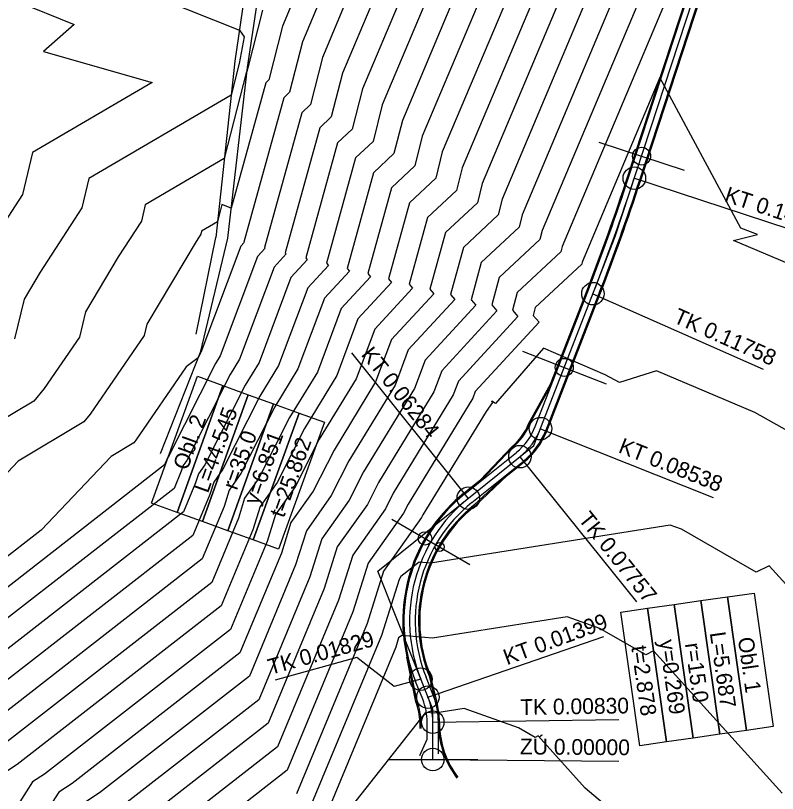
# Model space of a CAD drawing. Extents: x -549394 to -546608, y -1037055 to -1033629.
# Drawn here: x -548832.9 to -548663.6, y -1034374.1 to -1034201.2 of the extents above; entities that cross this region are included whole.
import ezdxf

# ---------------------------------------------------------------- set-up
doc = ezdxf.new("R2010")
doc.units = 0
for name, color, linetype in [('hlavni_vrst', 7, 'Continuous'), ('hrana_L', 7, 'Continuous'), ('norm_vrst', 7, 'Continuous'), ('POLYGONY_SITUACE_PO', 7, 'Continuous'), ('u_sirka_0_5m', 7, 'Continuous'), ('u_sirka_1_5m', 7, 'Continuous'), ('x_navrh_C122', 7, 'Continuous'), ('x_osa_C122', 7, 'Continuous'), ('x_popis_oblouky_C122', 7, 'Continuous'), ('x_popis_pricne_rezy_C122', 7, 'Continuous')]:
    doc.layers.add(name, color=color, linetype=linetype)

msp = doc.modelspace()

# ---------------------------------------------------------------- linework, layer by layer
at = {"layer": 'hlavni_vrst'}
for p, q in [((-548704.96, -1034195.08), (-548724.74, -1034242.04)), ((-548735.22, -1034196.67), (-548746.95, -1034224.54)), ((-548765.47, -1034198.27), (-548769.17, -1034207.05)), ((-548769.17, -1034207.05), (-548772.01, -1034218.28)), ((-548773.32, -1034219.5), (-548782.21, -1034251.62)), ((-548772.01, -1034218.28), (-548773.32, -1034219.5)), ((-548746.95, -1034224.54), (-548748.82, -1034231.91)), ((-548748.82, -1034231.91), (-548753.35, -1034236.16)), ((-548753.35, -1034236.16), (-548759.23, -1034257.42)), ((-548724.74, -1034242.04), (-548725.63, -1034245.55)), ((-548725.63, -1034245.55), (-548733.38, -1034252.81)), ((-548782.14, -1034251.7), (-548782.88, -1034252.51)), ((-548782.21, -1034251.62), (-548782.14, -1034251.7)), ((-548782.88, -1034252.51), (-548791.77, -1034276.13)), ((-548733.38, -1034252.81), (-548736.26, -1034263.23)), ((-548759.23, -1034257.42), (-548758.71, -1034258.01)), ((-548758.71, -1034258.01), (-548764.26, -1034264.03)), ((-548764.26, -1034264.03), (-548770.17, -1034279.76)), ((-548735.29, -1034264.33), (-548745.63, -1034275.56)), ((-548736.26, -1034263.23), (-548735.29, -1034264.33)), ((-548791.8, -1034276.18), (-548792.38, -1034277.32)), ((-548791.77, -1034276.13), (-548791.8, -1034276.18)), ((-548745.63, -1034275.56), (-548748.57, -1034283.39)), ((-548715.59, -1034275.15), (-548726.21, -1034287.49)), ((-548701.85, -1034281.06), (-548715.59, -1034275.15)), ((-548792.38, -1034277.32), (-548795, -1034279.32)), ((-548795, -1034279.32), (-548806.18, -1034295.61)), ((-548770.17, -1034279.76), (-548775.33, -1034288.2)), ((-548698.68, -1034282.78), (-548701.85, -1034281.06)), ((-548690.48, -1034280.2), (-548698.68, -1034282.78)), ((-548668.6, -1034289.46), (-548690.48, -1034280.2)), ((-548748.57, -1034283.39), (-548758.85, -1034300.21)), ((-548727.05, -1034286.95), (-548727.13, -1034286.99)), ((-548727.13, -1034286.99), (-548726.89, -1034287.22)), ((-548726.21, -1034287.49), (-548727.05, -1034286.95)), ((-548775.33, -1034288.2), (-548782.83, -1034303.04)), ((-548726.89, -1034287.22), (-548728.35, -1034289.27)), ((-548728.35, -1034289.27), (-548742.37, -1034312.23)), ((-548654.02, -1034297.71), (-548668.6, -1034289.46)), ((-548806.18, -1034295.61), (-548806.67, -1034296.2)), ((-548806.67, -1034296.2), (-548811.72, -1034299.21)), ((-548811.72, -1034299.21), (-548827.23, -1034315.61)), ((-548758.85, -1034300.21), (-548762.75, -1034307.93)), ((-548782.83, -1034303.04), (-548785.44, -1034306.72)), ((-548785.44, -1034306.72), (-548786.57, -1034310.32)), ((-548762.75, -1034307.93), (-548768.28, -1034315.73)), ((-548786.57, -1034310.32), (-548791.42, -1034322)), ((-548742.68, -1034312.83), (-548751.12, -1034324.74)), ((-548742.37, -1034312.23), (-548742.68, -1034312.83)), ((-548827.23, -1034315.61), (-548875.4, -1034353.08)), ((-548768.28, -1034315.73), (-548770.67, -1034323.35)), ((-548791.42, -1034322), (-548844.83, -1034363.54)), ((-548770.67, -1034323.35), (-548780.95, -1034348.1)), ((-548751.12, -1034324.74), (-548754.77, -1034336.39)), ((-548754.77, -1034336.39), (-548770.49, -1034374.21)), ((-548780.95, -1034348.1), (-548814.25, -1034374.01)), ((-548814.25, -1034374.01), (-548817.51, -1034376.13))]:
    msp.add_line(p, q, dxfattribs=at)
at = {"layer": 'hrana_L'}
for p, q in [((-548782.05, -1034196.95), (-548784.21, -1034211.37)), ((-548779.39, -1034199), (-548781.43, -1034212.74)), ((-548784.21, -1034211.37), (-548788.45, -1034250.58)), ((-548781.43, -1034212.74), (-548785.79, -1034250.71)), ((-548792.82, -1034272.02), (-548788.45, -1034250.58)), ((-548785.79, -1034250.71), (-548791.9, -1034276.11)), ((-548791.9, -1034276.11), (-548800.78, -1034298.66))]:
    msp.add_line(p, q, dxfattribs=at)
at = {"layer": 'norm_vrst'}
for p, q in [((-548698.91, -1034194.76), (-548720.29, -1034245.54)), ((-548692.86, -1034194.44), (-548715.85, -1034249.04)), ((-548686.81, -1034194.12), (-548711.41, -1034252.54)), ((-548741.27, -1034196.99), (-548751.4, -1034221.04)), ((-548729.17, -1034196.35), (-548742.51, -1034228.04)), ((-548723.11, -1034196.04), (-548738.07, -1034231.54)), ((-548717.06, -1034195.72), (-548733.62, -1034235.04)), ((-548711.01, -1034195.4), (-548729.18, -1034238.54)), ((-548832.73, -1034198.05), (-548819.92, -1034203.21)), ((-548800.85, -1034197.36), (-548783.18, -1034204.48)), ((-548771.52, -1034198.59), (-548773.61, -1034203.55)), ((-548759.42, -1034197.95), (-548764.73, -1034210.55)), ((-548753.37, -1034197.63), (-548760.28, -1034214.05)), ((-548747.32, -1034197.31), (-548755.84, -1034217.55)), ((-548778.06, -1034200.05), (-548781.29, -1034212.82)), ((-548819.92, -1034203.21), (-548826.7, -1034209.23)), ((-548773.61, -1034203.55), (-548776.65, -1034215.55)), ((-548783.18, -1034204.48), (-548782.11, -1034205.98)), ((-548782.11, -1034205.98), (-548783.22, -1034211.86)), ((-548826.7, -1034209.23), (-548802.58, -1034216.08)), ((-548764.73, -1034210.55), (-548767.37, -1034221)), ((-548783.22, -1034211.86), (-548785.03, -1034218.96)), ((-548781.59, -1034213.63), (-548786.55, -1034233.01)), ((-548781.53, -1034213.65), (-548781.59, -1034213.63)), ((-548781.31, -1034212.84), (-548781.53, -1034213.65)), ((-548781.29, -1034212.82), (-548781.31, -1034212.84)), ((-548760.28, -1034214.05), (-548762.74, -1034223.73)), ((-548802.58, -1034216.08), (-548829.17, -1034231.66)), ((-548776.65, -1034215.55), (-548777.32, -1034216.17)), ((-548689.68, -1034214.99), (-548706.96, -1034256.04)), ((-548671.73, -1034248.5), (-548689.68, -1034214.99)), ((-548777.32, -1034216.17), (-548785.02, -1034244.03)), ((-548755.84, -1034217.55), (-548758.1, -1034226.46)), ((-548785.03, -1034218.96), (-548816.64, -1034237.48)), ((-548767.37, -1034221), (-548769.33, -1034222.83)), ((-548751.4, -1034221.04), (-548753.46, -1034229.19)), ((-548769.33, -1034222.83), (-548777.61, -1034252.78)), ((-548762.74, -1034223.73), (-548765.33, -1034226.16)), ((-548765.33, -1034226.16), (-548773.02, -1034253.94)), ((-548758.1, -1034226.46), (-548761.34, -1034229.49)), ((-548742.51, -1034228.04), (-548744.18, -1034234.64)), ((-548761.34, -1034229.49), (-548768.42, -1034255.1)), ((-548753.46, -1034229.19), (-548757.35, -1034232.83)), ((-548829.17, -1034231.66), (-548831.41, -1034241.01)), ((-548738.07, -1034231.54), (-548739.54, -1034237.37)), ((-548786.55, -1034233.01), (-548804.11, -1034243.3)), ((-548757.35, -1034232.83), (-548763.83, -1034256.26)), ((-548744.18, -1034234.64), (-548749.36, -1034239.49)), ((-548733.62, -1034235.04), (-548734.9, -1034240.1)), ((-548816.64, -1034237.48), (-548818.19, -1034243.95)), ((-548739.54, -1034237.37), (-548745.36, -1034242.82)), ((-548729.18, -1034238.54), (-548730.26, -1034242.82)), ((-548749.36, -1034239.49), (-548754.64, -1034258.58)), ((-548734.9, -1034240.1), (-548741.37, -1034246.15)), ((-548831.41, -1034241.01), (-548844.45, -1034261.12)), ((-548804.11, -1034243.3), (-548804.97, -1034246.9)), ((-548787.08, -1034243.19), (-548788.07, -1034247.07)), ((-548785.02, -1034244.03), (-548787.08, -1034243.19)), ((-548745.36, -1034242.82), (-548750.05, -1034259.74)), ((-548730.26, -1034242.82), (-548737.38, -1034249.48)), ((-548818.19, -1034243.95), (-548827.46, -1034258.25)), ((-548804.97, -1034246.9), (-548810.12, -1034254.84)), ((-548788.07, -1034247.07), (-548791.58, -1034249.12)), ((-548741.37, -1034246.15), (-548745.45, -1034260.9)), ((-548720.29, -1034245.54), (-548720.99, -1034248.28)), ((-548720.99, -1034248.28), (-548729.39, -1034256.14)), ((-548667.97, -1034249.87), (-548671.73, -1034248.5)), ((-548791.75, -1034249.84), (-548792.78, -1034251.43)), ((-548791.58, -1034249.12), (-548791.75, -1034249.84)), ((-548737.38, -1034249.48), (-548740.86, -1034262.07)), ((-548715.85, -1034249.04), (-548716.35, -1034251.01)), ((-548673.3, -1034251.25), (-548667.97, -1034249.87)), ((-548792.78, -1034251.43), (-548803.75, -1034269.81)), ((-548716.35, -1034251.01), (-548725.39, -1034259.47)), ((-548654.22, -1034259.32), (-548673.3, -1034251.25)), ((-548777.45, -1034252.96), (-548779.16, -1034254.81)), ((-548777.61, -1034252.78), (-548777.45, -1034252.96)), ((-548773.02, -1034253.94), (-548772.77, -1034254.22)), ((-548711.71, -1034253.73), (-548721.4, -1034262.8)), ((-548711.41, -1034252.54), (-548711.71, -1034253.73)), ((-548810.12, -1034254.84), (-548817.41, -1034267.05)), ((-548779.16, -1034254.81), (-548787.45, -1034276.86)), ((-548772.77, -1034254.22), (-548775.43, -1034257.12)), ((-548768.08, -1034255.49), (-548771.71, -1034259.42)), ((-548768.42, -1034255.1), (-548768.08, -1034255.49)), ((-548775.43, -1034257.12), (-548783.13, -1034277.58)), ((-548763.4, -1034256.75), (-548767.98, -1034261.73)), ((-548763.83, -1034256.26), (-548763.4, -1034256.75)), ((-548729.39, -1034256.14), (-548731.67, -1034264.39)), ((-548707.07, -1034256.46), (-548717.41, -1034266.14)), ((-548706.96, -1034256.04), (-548707.07, -1034256.46)), ((-548827.46, -1034258.25), (-548831.06, -1034264.29)), ((-548754.03, -1034259.28), (-548760.53, -1034266.34)), ((-548754.64, -1034258.58), (-548754.03, -1034259.28)), ((-548771.71, -1034259.42), (-548778.81, -1034278.31)), ((-548749.34, -1034260.54), (-548756.81, -1034268.64)), ((-548750.05, -1034259.74), (-548749.34, -1034260.54)), ((-548745.45, -1034260.9), (-548744.66, -1034261.81)), ((-548725.39, -1034259.47), (-548727.07, -1034265.55)), ((-548767.98, -1034261.73), (-548774.49, -1034279.04)), ((-548744.66, -1034261.81), (-548753.08, -1034270.95)), ((-548740.86, -1034262.07), (-548739.98, -1034263.07)), ((-548721.4, -1034262.8), (-548722.48, -1034266.71)), ((-548831.06, -1034264.29), (-548833.16, -1034273.12)), ((-548739.98, -1034263.07), (-548749.35, -1034273.25)), ((-548731.67, -1034264.39), (-548730.61, -1034265.6)), ((-548730.61, -1034265.6), (-548741.9, -1034277.86)), ((-548727.07, -1034265.55), (-548725.92, -1034266.86)), ((-548717.41, -1034266.14), (-548717.89, -1034267.87)), ((-548817.41, -1034267.05), (-548818.75, -1034272.73)), ((-548760.53, -1034266.34), (-548765.85, -1034280.49)), ((-548725.92, -1034266.86), (-548738.18, -1034280.17)), ((-548722.48, -1034266.71), (-548721.24, -1034268.12)), ((-548717.89, -1034267.87), (-548716.55, -1034269.39)), ((-548756.81, -1034268.64), (-548761.53, -1034281.21)), ((-548721.24, -1034268.12), (-548734.45, -1034282.47)), ((-548716.55, -1034269.39), (-548730.73, -1034284.78)), ((-548803.75, -1034269.81), (-548804.35, -1034272.34)), ((-548753.08, -1034270.95), (-548757.21, -1034281.94)), ((-548818.75, -1034272.73), (-548826.56, -1034284.1)), ((-548804.35, -1034272.34), (-548816.37, -1034289.86)), ((-548749.35, -1034273.25), (-548752.89, -1034282.66)), ((-548787.45, -1034276.86), (-548788.51, -1034278.59)), ((-548783.13, -1034277.58), (-548785.21, -1034280.99)), ((-548778.81, -1034278.31), (-548781.92, -1034283.39)), ((-548741.9, -1034277.86), (-548744.26, -1034284.12)), ((-548788.51, -1034278.59), (-548798.89, -1034299.12)), ((-548774.49, -1034279.04), (-548778.62, -1034285.8)), ((-548785.21, -1034280.99), (-548794.88, -1034300.1)), ((-548765.85, -1034280.49), (-548772.03, -1034290.6)), ((-548761.53, -1034281.21), (-548768.74, -1034293)), ((-548738.18, -1034280.17), (-548739.94, -1034284.84)), ((-548781.92, -1034283.39), (-548790.86, -1034301.08)), ((-548757.21, -1034281.94), (-548765.44, -1034295.41)), ((-548752.89, -1034282.66), (-548762.14, -1034297.81)), ((-548734.45, -1034282.47), (-548735.62, -1034285.57)), ((-548826.56, -1034284.1), (-548828.91, -1034286.91)), ((-548744.26, -1034284.12), (-548755.55, -1034302.62)), ((-548739.94, -1034284.84), (-548752.26, -1034305.02)), ((-548730.73, -1034284.78), (-548731.3, -1034286.29)), ((-548828.91, -1034286.91), (-548852.99, -1034301.31)), ((-548778.62, -1034285.8), (-548786.85, -1034302.06)), ((-548735.62, -1034285.57), (-548748.96, -1034307.42)), ((-548731.3, -1034286.29), (-548745.67, -1034309.83)), ((-548816.37, -1034289.86), (-548817.79, -1034291.55)), ((-548817.79, -1034291.55), (-548832.35, -1034300.26)), ((-548772.03, -1034290.6), (-548778.82, -1034304.02)), ((-548768.74, -1034293), (-548774.8, -1034305)), ((-548765.44, -1034295.41), (-548770.78, -1034305.97)), ((-548798.89, -1034299.12), (-548799.17, -1034299.51)), ((-548762.14, -1034297.81), (-548766.77, -1034306.95)), ((-548832.35, -1034300.26), (-548877.14, -1034347.58)), ((-548799.29, -1034299.89), (-548799.8, -1034301.11)), ((-548799.17, -1034299.51), (-548799.29, -1034299.89)), ((-548794.88, -1034300.1), (-548795.74, -1034301.31)), ((-548799.8, -1034301.11), (-548869.29, -1034355.17)), ((-548796.11, -1034302.49), (-548797.7, -1034306.33)), ((-548795.74, -1034301.31), (-548796.11, -1034302.49)), ((-548790.86, -1034301.08), (-548792.3, -1034303.11)), ((-548786.85, -1034302.06), (-548788.87, -1034304.91)), ((-548792.3, -1034303.11), (-548792.93, -1034305.1)), ((-548778.82, -1034304.02), (-548782.01, -1034308.52)), ((-548755.55, -1034302.62), (-548758.74, -1034308.91)), ((-548792.93, -1034305.1), (-548795.61, -1034311.56)), ((-548788.87, -1034304.91), (-548789.75, -1034307.71)), ((-548774.8, -1034305), (-548778.58, -1034310.32)), ((-548770.78, -1034305.97), (-548775.15, -1034312.13)), ((-548752.26, -1034305.02), (-548754.72, -1034309.89)), ((-548797.7, -1034306.33), (-548863.17, -1034357.27)), ((-548789.75, -1034307.71), (-548793.52, -1034316.78)), ((-548766.77, -1034306.95), (-548771.71, -1034313.93)), ((-548748.96, -1034307.42), (-548750.71, -1034310.87)), ((-548782.01, -1034308.52), (-548783.39, -1034312.92)), ((-548758.74, -1034308.91), (-548764.85, -1034317.53)), ((-548778.58, -1034310.32), (-548780.21, -1034315.53)), ((-548754.72, -1034309.89), (-548761.42, -1034319.34)), ((-548750.71, -1034310.87), (-548757.99, -1034321.14)), ((-548745.67, -1034309.83), (-548746.69, -1034311.85)), ((-548795.61, -1034311.56), (-548857.06, -1034359.36)), ((-548783.39, -1034312.92), (-548789.33, -1034327.22)), ((-548775.15, -1034312.13), (-548777.03, -1034318.14)), ((-548746.69, -1034311.85), (-548754.56, -1034322.94)), ((-548771.71, -1034313.93), (-548773.85, -1034320.75)), ((-548687.4, -1034314.52), (-548740.71, -1034322.92)), ((-548684.92, -1034315.39), (-548687.4, -1034314.52)), ((-548780.21, -1034315.53), (-548787.23, -1034332.44)), ((-548668.27, -1034324.97), (-548684.92, -1034315.39)), ((-548793.52, -1034316.78), (-548850.94, -1034361.45)), ((-548777.03, -1034318.14), (-548785.14, -1034337.66)), ((-548764.85, -1034317.53), (-548767.49, -1034325.96)), ((-548761.42, -1034319.34), (-548764.31, -1034328.57)), ((-548773.85, -1034320.75), (-548783.05, -1034342.88)), ((-548757.99, -1034321.14), (-548761.13, -1034331.17)), ((-548754.56, -1034322.94), (-548757.95, -1034333.78)), ((-548743.22, -1034322.7), (-548747.27, -1034325.94)), ((-548740.71, -1034322.92), (-548743.22, -1034322.7)), ((-548665.39, -1034323.55), (-548668.27, -1034324.97)), ((-548630.74, -1034361.88), (-548665.39, -1034323.55)), ((-548767.49, -1034325.96), (-548778.86, -1034353.32)), ((-548747.69, -1034326.55), (-548751.59, -1034339)), ((-548747.27, -1034325.94), (-548747.69, -1034326.55)), ((-548789.33, -1034327.22), (-548838.71, -1034365.64)), ((-548764.31, -1034328.57), (-548776.77, -1034358.54)), ((-548761.13, -1034331.17), (-548774.67, -1034363.76)), ((-548787.23, -1034332.44), (-548832.6, -1034367.73)), ((-548757.95, -1034333.78), (-548772.58, -1034368.98)), ((-548710.3, -1034334.9), (-548740.22, -1034339.62)), ((-548703.04, -1034337.46), (-548710.3, -1034334.9)), ((-548785.14, -1034337.66), (-548826.48, -1034369.82)), ((-548692.84, -1034343.32), (-548703.04, -1034337.46)), ((-548751.59, -1034339), (-548768.39, -1034379.43)), ((-548747.77, -1034339.56), (-548748.41, -1034341.6)), ((-548747.08, -1034339), (-548747.77, -1034339.56)), ((-548740.22, -1034339.62), (-548747.08, -1034339)), ((-548748.41, -1034341.6), (-548766.3, -1034384.65)), ((-548783.05, -1034342.88), (-548820.37, -1034371.91)), ((-548691.08, -1034342.45), (-548692.84, -1034343.32)), ((-548662.5, -1034374.07), (-548691.08, -1034342.45)), ((-548778.86, -1034353.32), (-548808.14, -1034376.1)), ((-548759.56, -1034378.68), (-548741.71, -1034356.14)), ((-548739.74, -1034356.32), (-548741.71, -1034356.14)), ((-548733.19, -1034355.28), (-548739.74, -1034356.32)), ((-548721.16, -1034359.52), (-548733.19, -1034355.28)), ((-548776.77, -1034358.54), (-548802.02, -1034378.19)), ((-548717.42, -1034361.68), (-548721.16, -1034359.52)), ((-548716.77, -1034361.36), (-548717.42, -1034361.68)), ((-548706.28, -1034372.96), (-548716.77, -1034361.36)), ((-548774.67, -1034363.76), (-548795.91, -1034380.28)), ((-548832.6, -1034367.73), (-548834.97, -1034369.28)), ((-548826.48, -1034369.82), (-548829.15, -1034371.56)), ((-548772.58, -1034368.98), (-548789.79, -1034382.37)), ((-548829.15, -1034371.56), (-548842.47, -1034392.22)), ((-548820.37, -1034371.91), (-548823.33, -1034373.85)), ((-548664.52, -1034408.24), (-548706.28, -1034372.96)), ((-548823.33, -1034373.85), (-548838.11, -1034396.77))]:
    msp.add_line(p, q, dxfattribs=at)
at = {"layer": 'POLYGONY_SITUACE_PO'}
for centre in [(-548695.37, -1034237.37), (-548704.57, -1034263.05), (-548716.24, -1034293.05), (-548720.81, -1034299.28), (-548732.28, -1034308.52), (-548742.85, -1034348.75), (-548741.26, -1034352.75), (-548740.19, -1034358.3), (-548740.19, -1034366.6)]:
    msp.add_circle(centre, 2.5, dxfattribs=at)
at = {"layer": 'u_sirka_0_5m'}
for centre in [(-548693.77, -1034232.48), (-548710.94, -1034279.43)]:
    msp.add_circle(centre, 2, dxfattribs=at)
at = {"layer": 'u_sirka_1_5m'}
for centre, radius in [((-548741.9, -1034317.45), 1.5), ((-548738.66, -1034319.33), 1)]:
    msp.add_circle(centre, radius, dxfattribs=at)
at = {"layer": 'x_navrh_C122'}
for p, q in [((-548696.56, -1034236.98), (-548681.92, -1034192.29)), ((-548694.18, -1034237.76), (-548679.54, -1034193.07)), ((-548717.4, -1034292.59), (-548705.73, -1034262.6)), ((-548715.07, -1034293.5), (-548703.4, -1034263.5)), ((-548718.91, -1034291.99), (-548714, -1034283.16)), ((-548718.68, -1034292.09), (-548713.78, -1034283.27)), ((-548722.63, -1034297.07), (-548729.56, -1034304.4)), ((-548722.46, -1034297.25), (-548729.39, -1034304.59)), ((-548733.07, -1034307.55), (-548721.6, -1034298.32)), ((-548731.5, -1034309.49), (-548720.03, -1034300.26)), ((-548731.03, -1034310.08), (-548723.71, -1034303.22)), ((-548730.87, -1034310.27), (-548723.54, -1034303.41)), ((-548743.93, -1034353.79), (-548745.95, -1034343.82)), ((-548743.69, -1034353.72), (-548745.71, -1034343.77)), ((-548742.42, -1034353.21), (-548744.02, -1034349.22)), ((-548740.1, -1034352.29), (-548741.69, -1034348.29)), ((-548741, -1034348.01), (-548739.62, -1034353.68)), ((-548740.76, -1034347.92), (-548739.38, -1034353.61)), ((-548739.23, -1034355.24), (-548739.23, -1034355.25)), ((-548743.06, -1034358.31), (-548743.06, -1034359.68)), ((-548742.81, -1034358.31), (-548742.81, -1034359.68)), ((-548741.44, -1034362.06), (-548741.44, -1034358.31)), ((-548738.94, -1034365.31), (-548738.94, -1034358.31)), ((-548743.07, -1034365.69), (-548741.44, -1034362.06))]:
    msp.add_line(p, q, dxfattribs=at)
for points in [[(-548696.8, -1034236.9), (-548682.16, -1034192.21)], [(-548693.94, -1034237.83), (-548679.31, -1034193.15)], [(-548714, -1034283.16), (-548705.96, -1034262.51)], [(-548714.84, -1034293.59), (-548703.17, -1034263.59)], [(-548723.54, -1034303.41), (-548719.87, -1034300.46)], [(-548733.22, -1034307.35), (-548729.56, -1034304.4)], [(-548738.69, -1034358.52), (-548738.69, -1034358.31)]]:
    msp.add_lwpolyline(points, dxfattribs=at)
for centre, radius, start, end in [((-549170.53, -1034081.72), 498.5, 338.7363, 341.8627), ((-549170.53, -1034081.72), 498.75, 338.7363, 341.8627), ((-549170.53, -1034081.72), 501.25, 338.7363, 341.8627), ((-549170.53, -1034081.72), 501.5, 338.7363, 341.8627), ((-548730.22, -1034287.6), 12.13, 308.7397, 338.8164), ((-548730.22, -1034287.6), 12.38, 308.8198, 338.7363), ((-548730.22, -1034287.6), 13.75, 308.8198, 338.7363), ((-548730.22, -1034287.6), 16.25, 308.8198, 338.7363), ((-548730.22, -1034287.6), 16.5, 308.8198, 338.7363), ((-548710.34, -1034335.79), 36.5, 128.8198, 192.7089), ((-548710.34, -1034335.79), 36.25, 128.8198, 201.7415), ((-548710.34, -1034335.79), 33.75, 128.8198, 201.7415), ((-548710.34, -1034335.79), 33, 128.8198, 201.7415), ((-548710.34, -1034335.79), 32.75, 128.8198, 201.7415), ((-548755.19, -1034358.31), 16.25, 0, 21.7415), ((-548755.19, -1034358.31), 12.13, 0, 21.8476), ((-548755.19, -1034358.31), 12.38, 0, 21.7415), ((-548755.19, -1034358.31), 13.75, 0, 21.7415), ((-548755.19, -1034358.31), 16.5, 0, 16.5484), ((-548718.94, -1034358.52), 20, 180, 217.5364), ((-548718.94, -1034358.52), 19.75, 180, 217.5364)]:
    msp.add_arc(centre, radius, start, end, dxfattribs=at)
at = {"layer": 'x_osa_C122'}
for points in [[(-548717.69, -1034296.78), (-548699.62, -1034250.33), (-548699.62, -1034250.33), (-548677.63, -1034183.22), (-548677.63, -1034183.22), (-548677.63, -1034183.22), (-548664.6, -1034152.07), (-548606, -1034092.26), (-548545.79, -1034027.23)], [(-548752.43, -1034324.73), (-548717.69, -1034296.78)], [(-548740.19, -1034355.42), (-548752.43, -1034324.73)], [(-548740.19, -1034366.6), (-548740.19, -1034355.42)]]:
    msp.add_lwpolyline(points, dxfattribs=at)
for centre, radius, start, end in [((-549170.53, -1034081.72), 500, 338.7363, 341.8627), ((-548730.22, -1034287.6), 15, 308.8198, 338.7363), ((-548710.34, -1034335.79), 35, 128.8198, 201.7415), ((-548755.19, -1034358.31), 15, 0, 21.7415)]:
    msp.add_arc(centre, radius, start, end, dxfattribs=at)
at = {"layer": 'x_popis_oblouky_C122'}
for points in [[(-548695.37, -1034237.37), (-548656.05, -1034250.25)], [(-548704.57, -1034263.05), (-548666.75, -1034279.84)], [(-548732.28, -1034308.52), (-548758.15, -1034276.23)], [(-548716.24, -1034293.06), (-548677.81, -1034308.38)], [(-548720.81, -1034299.28), (-548694.87, -1034331.52)], [(-548741.26, -1034352.75), (-548702.15, -1034339.26)], [(-548748.79, -1034350.4), (-548757.09, -1034343.92), (-548775.23, -1034348.94)], [(-548742.85, -1034348.75), (-548748.79, -1034350.4)], [(-548740.19, -1034358.3), (-548698.83, -1034357.67)], [(-548740.19, -1034366.6), (-548698.82, -1034366.93)]]:
    msp.add_lwpolyline(points, dxfattribs=at)
for points in [[(-548802.69, -1034309.63), (-548792.48, -1034281.42), (-548786.84, -1034283.47), (-548797.05, -1034311.68)], [(-548797.05, -1034311.68), (-548786.84, -1034283.47), (-548781.2, -1034285.51), (-548791.41, -1034313.72)], [(-548791.41, -1034313.72), (-548781.2, -1034285.51), (-548775.56, -1034287.55), (-548785.77, -1034315.76)], [(-548785.77, -1034315.76), (-548775.56, -1034287.55), (-548769.92, -1034289.59), (-548780.12, -1034317.8)], [(-548780.12, -1034317.8), (-548769.92, -1034289.59), (-548764.27, -1034291.63), (-548774.48, -1034319.84)], [(-548668.7, -1034329.59), (-548664.47, -1034359.29), (-548670.41, -1034360.14), (-548674.64, -1034330.43)], [(-548680.58, -1034331.28), (-548676.35, -1034360.98), (-548682.29, -1034361.83), (-548686.52, -1034332.13)], [(-548674.64, -1034330.43), (-548670.41, -1034360.14), (-548676.35, -1034360.98), (-548680.58, -1034331.28)], [(-548692.46, -1034332.97), (-548688.23, -1034362.67), (-548694.17, -1034363.52), (-548698.4, -1034333.82)], [(-548686.52, -1034332.13), (-548682.29, -1034361.83), (-548688.23, -1034362.67), (-548692.46, -1034332.97)]]:
    msp.add_lwpolyline(points, close=True, dxfattribs=at)
at = {"layer": 'x_popis_pricne_rezy_C122'}
for points in [[(-548703.27, -1034229.37), (-548693.77, -1034232.48), (-548684.27, -1034235.6)], [(-548720.26, -1034275.8), (-548710.94, -1034279.43), (-548701.62, -1034283.06)], [(-548749.25, -1034313.18), (-548740.6, -1034318.2), (-548731.96, -1034323.23)], [(-548750.19, -1034366.6), (-548740.19, -1034366.6), (-548730.19, -1034366.6)]]:
    msp.add_lwpolyline(points, dxfattribs=at)

# ---------------------------------------------------------------- texts
at = {"layer": 'x_popis_oblouky_C122'}
for s, rotation, p in [('KT 0.14486', 341.8627, (-548675.55, -1034242.49)), ('TK 0.11758', 336.0588, (-548686.95, -1034269.34)), ('KT 0.06284', 308.6899, (-548756.27, -1034276.64)), ('L=44.545', 70.1278, (-548790.18, -1034307.56)), ('Obl. 2', 70.1278, (-548794.74, -1034302.5)), ('r=35.0', 70.1278, (-548783.75, -1034306.91)), ('y=6.851', 70.1278, (-548779.04, -1034310.23)), ('t=25.862', 70.1278, (-548773.31, -1034313.05)), ('KT 0.08538', 338.2602, (-548699.13, -1034298.25)), ('TK 0.07757', 308.816, (-548707.98, -1034313.25)), ('KT 0.01399', 20.1821, (-548723.7, -1034345.64)), ('TK 0.01829', 15.5252, (-548776.26, -1034347.78)), ('L=5.687', 278.126, (-548678.6, -1034338.44)), ('y=0.269', 278.126, (-548689.86, -1034340.17)), ('Obl. 1', 278.126, (-548672.37, -1034339.62)), ('t=2.878', 278.126, (-548696.08, -1034341.52)), ('r=15.0', 278.126, (-548684.14, -1034340.88)), ('TK 0.00830', 0.8703, (-548720.73, -1034356.7)), ('ZÚ 0.00000', 359.5512, (-548720.82, -1034365.45))]:
    msp.add_text(s, height=3.5, rotation=rotation, dxfattribs=at).set_placement(p)

doc.saveas('drawing.dxf')
